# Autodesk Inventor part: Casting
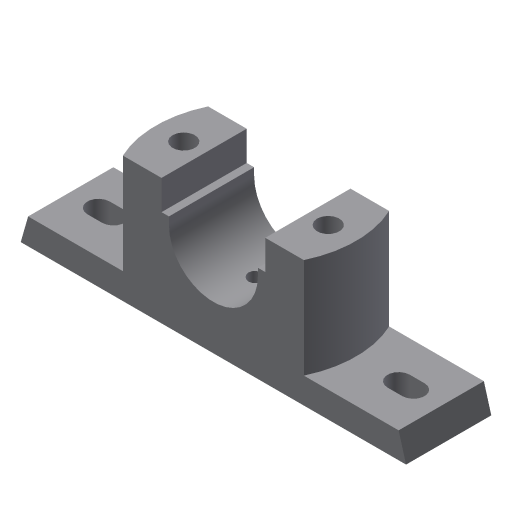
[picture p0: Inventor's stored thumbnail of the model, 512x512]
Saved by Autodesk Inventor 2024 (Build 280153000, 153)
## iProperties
Created: 2009-04
Part Number: Casting
Document SubType Name: Modeling
Designer: Sham
Density: 1 g/cm^3
Material: Generic
Appearance: Default
Author: Sham
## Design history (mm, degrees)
sketch "Sketch1"
  geometry: L1 (-104, 0)-(104, 0); L2 (-104, 0)-(-100, 14); L3 (-100, 14)-(100, 14); L4 (100, 14)-(104, 0); 1 further point
  constraints: 8 end point, 1 horizontal, 1 midpoint, 1 parallel, 1 other
  dimensions: "d0" = 208 distance of L1.start L1.end; "d1" = 104 distance of L1.end point (0, 0); "d2" = 4 horizontal distance of L1.start L2.end; "d3" = 4 horizontal distance of L1.end L3.end; "d10" = 14 distance between parallel lines of L1 L3
extrude "Extrusion1" new body sketch "Sketch1" stored distance "d4" = 46; taper "d5" = 0 deg
sketch "Sketch2"
  geometry: L1 (51.143, 46)-(148.857, 46); L2 (148.857, 0)-(51.143, 0); A1 r 54 centre (100, 23) between (51.143, 46) and (51.143, 0); A2 r 54 centre (100, 23) between (148.857, 0) and (148.857, 46)
  constraints: 4 end point, 4 point on circle, 2 centre point, 1 parallel
extrude "Extrusion2" join sketch "Sketch2" distance "d8" = 54; taper "d9" = 0 deg
sketch "Sketch3"
  geometry: L1 (-28, 68)-(-28, 52); L2 (-28, 52)-(-24, 52); L3 (28, 68)-(28, 52); L4 (28, 52)-(24, 52); L5 (-28, 68)-(28, 68); L6 (-100, 14)-(-48.857, 14) reference; L7 (0, 48)-(0, 19); L8 (48.857, 14)-(100, 14) reference; L9 (48.857, 68)-(-48.857, 68) reference; L10 (-24, 48)-(-24, 52); L11 (24, 48)-(24, 52); A1 r 24 centre (0, 48) between (-24, 48) and (24, 48); 1 further point
  constraints: 16 end point, 5 perpendicular, 2 point on circle, 2 symmetric about line, 1 centre point, 1 tangent, 1 vertical alignment, 1 other
  dimensions: "d11" = 16 distance of L1.start L1.end; "d16" = 24 radius of A1; "d17" = 16 distance of L3.start L3.end; "d52" = 56 distance between parallel lines of L1 L3; "d54" = 54 distance between parallel lines of L8 L9 (derived)
extrude "Extrusion3" cut sketch "Sketch3" distance "d18" = 54; taper "d19" = 0 deg
sketch "Sketch4"
  geometry: L1 (-23, 29)-(-15, 29); L2 (-15, 17)-(-23, 17); L3 (-185, 29)-(-177, 29); L4 (-177, 17)-(-185, 17); A1 r 6 centre (-15, 23) between (-15, 17) and (-15, 29); A2 r 6 centre (-23, 23) between (-23, 29) and (-23, 17); A3 r 6 centre (-177, 23) between (-177, 17) and (-177, 29); A4 r 6 centre (-185, 23) between (-185, 29) and (-185, 17)
  constraints: 8 end point, 8 point on circle, 8 tangent, 4 centre point, 3 parallel
  dimensions: "d20" = 8 distance of A1.centre A2.centre; "d21" = 6 radius of A1; "d24" = 6 radius of A3; "d25" = 8 distance of A4.centre A3.centre
extrude "Extrusion4" cut sketch "Sketch4" distance "d28" = 54; taper "d29" = 0 deg
sketch "Sketch5"
  geometry: L1 (208, 0)-(0, 0) reference; L2 (52, -10)-(78, -10); L3 (78, -10)-(78, -36); L4 (78, -36)-(52, -36); L5 (52, -36)-(52, -10); L6 (130, -10)-(156, -10); L7 (156, -10)-(156, -36); L8 (156, -36)-(130, -36); L9 (130, -36)-(130, -10); L10 (0, -46)-(208, -46) reference; L11 (104, -23)-(104, -46)
  constraints: 18 end point, 5 perpendicular, 4 parallel, 2 horizontal, 1 midpoint
  dimensions: "d30" = 26 distance of L2.start L2.end; "d31" = 10 distance between parallel lines of L2 L1; "d32" = 10 distance between parallel lines of L1 L6; "d65" = 26 distance between parallel lines of L3 L11; "d66" = 26 distance between parallel lines of L9 L11
extrude "Extrusion5" cut sketch "Sketch5" distance "d34" = 10; taper "d35" = 0 deg
sketch "Sketch6"
  geometry: L1 (148.857, 0)-(128, 0) reference; L2 (72, 0)-(51.143, 0) reference; L3 (0, 46)-(0, 0) reference; L4 (200, 46)-(200, 0) reference; C1 r 6 at (61, 23); C2 r 6 at (139, 23); 1 further point
  constraints: 2 centre point, 1 equal radius
  dimensions: "d36" = 12 diameter of C1; "d37" = 78 distance of C2.centre C1.centre; "d39" = 39 distance of C2.centre point (100, 23); "d58" = 39 distance of C1.centre point (100, 23); "d59" = 23 distance from line of L1 C2.centre; "d60" = 23 distance from line of L2 C1.centre; "d61" = 61 distance from line of L3 C1.centre; "d62" = 61 distance from line of L4 C2.centre (derived)
extrude "Extrusion6" cut sketch "Sketch6" extent not by distance; stored distance "d40" = 10; taper "d41" = 0 deg
workplane "Work Plane1"
sketch "Sketch7"
  geometry: L1 (-4, 46)-(204, 46) reference; L2 (-4, 0)-(-4, 46) reference; 1 further point
  dimensions: "d43" = 23 distance from line of L1 point (100, 23); "d44" = 104 distance from line of point (100, 23) L2
hole "Hole1" sketch "Sketch7" diameter "d45" = 8; stored, may be unused: countersink angle "d49" = 90 deg, drill point angle "d51" = 118 deg; dims "d46" = 6, "d47" = 8, "d48" = 16, "d50" = 8
body "Solid1"
other parameters: "d6" = 108, "d42" = -52
